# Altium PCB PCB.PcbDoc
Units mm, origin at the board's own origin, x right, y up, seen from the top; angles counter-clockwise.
Board outline 41 x 25.36 mm, 2 copper layers (TOP, BOTTOM), stack 1.586 mm thick; 64 components, 42 nets, 181 pads, 89 vias.
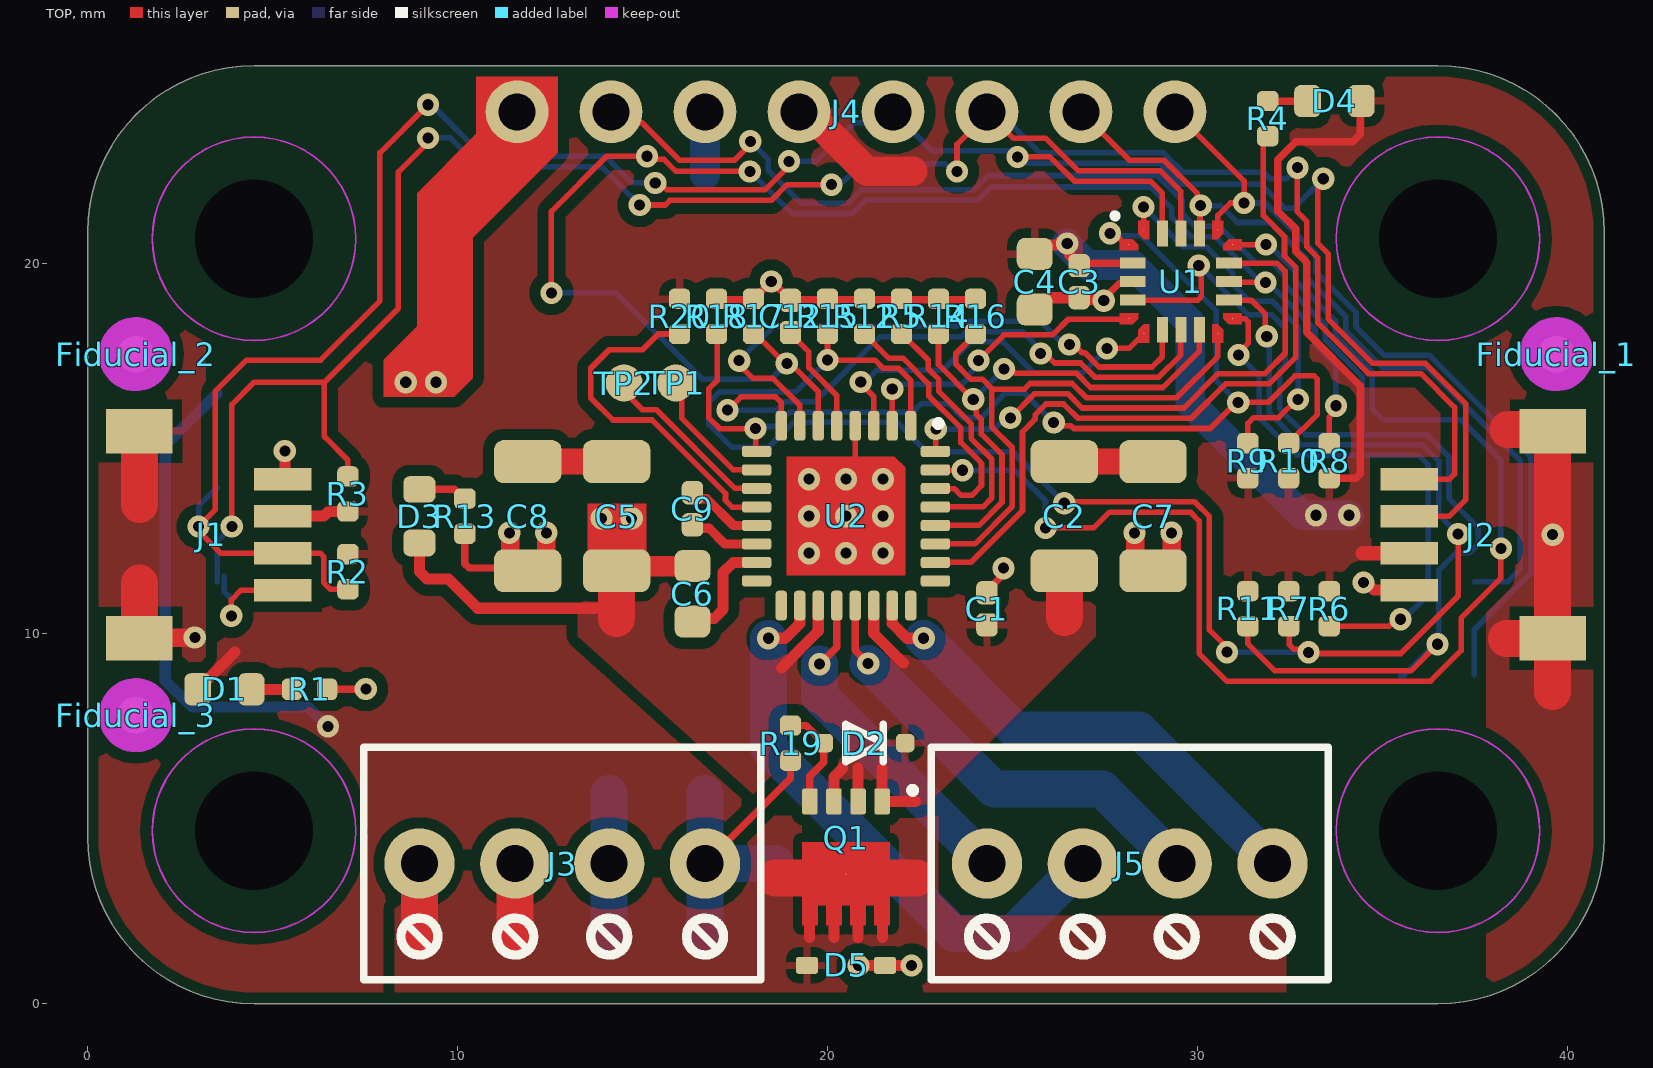
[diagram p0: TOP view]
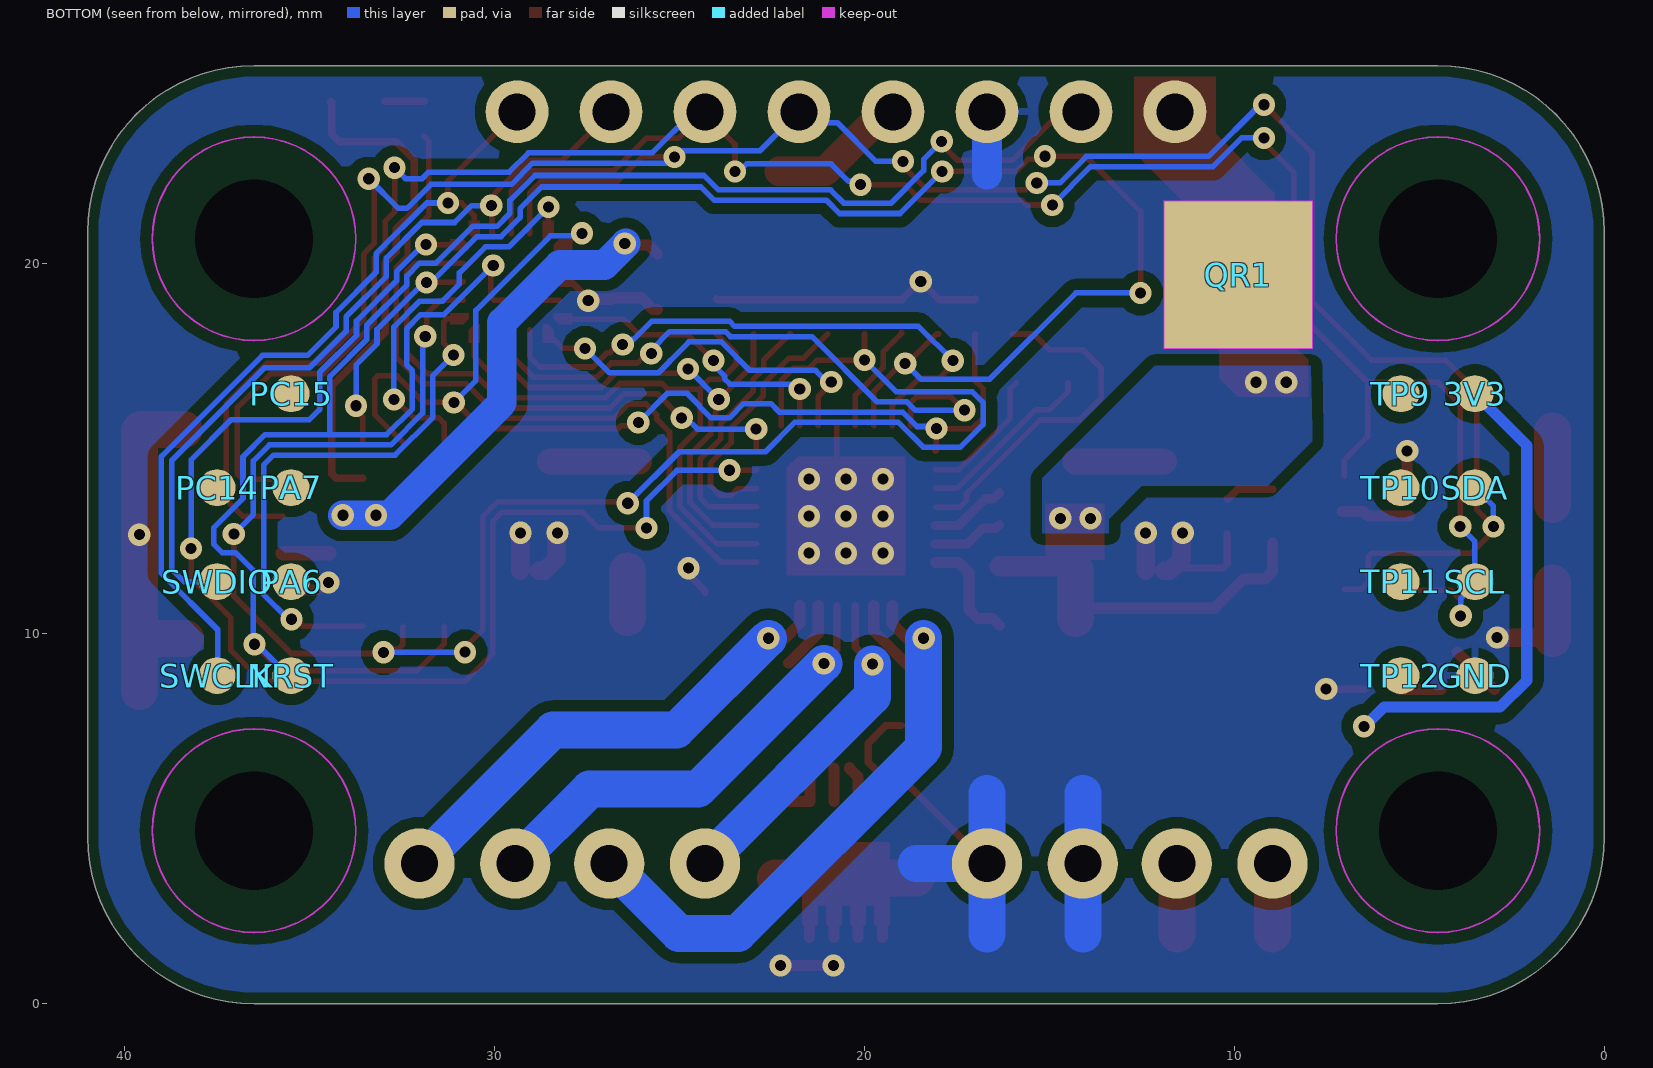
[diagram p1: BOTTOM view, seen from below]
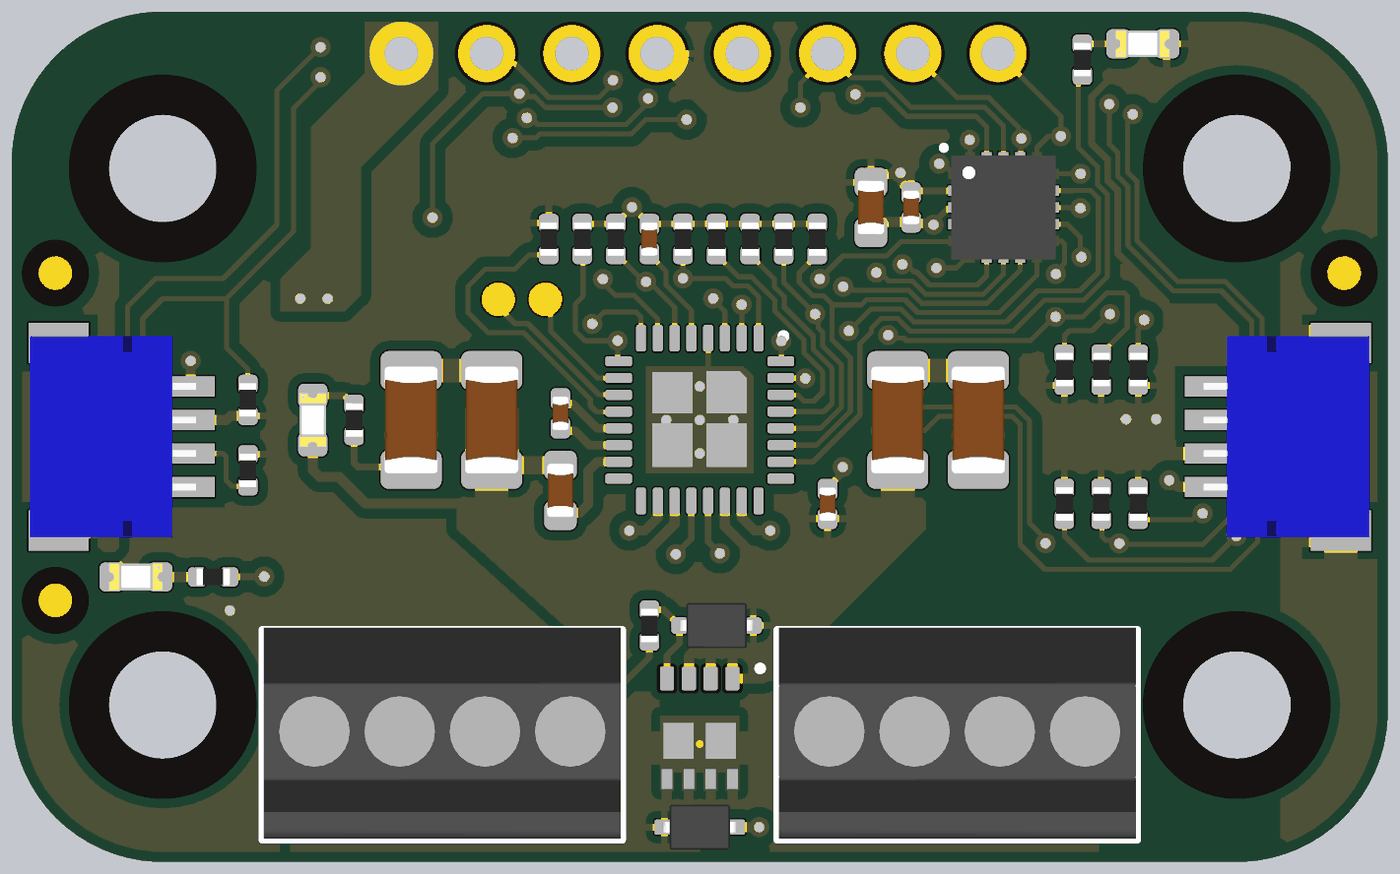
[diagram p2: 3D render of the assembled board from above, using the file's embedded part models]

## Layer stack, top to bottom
Top Solder: solder mask 0.01, Solder Resist, Dk 3.5
TOP: signal copper 0.018
Dielectric: core 1.55, FR-4, Dk 4.8
BOTTOM: signal copper 0.018
Bottom Solder: solder mask 0.01, Solder Resist, Dk 3.5

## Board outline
0,4.5 ccw(c4.5,4.5) 4.5,0 36.5,0 ccw(c36.5,4.5) 41,4.5 41,20.86 ccw(c36.5,20.86) 36.5,25.36 4.5,25.36 ccw(c4.5,20.86) 0,20.86

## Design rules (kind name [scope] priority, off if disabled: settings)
BoardOutlineClearance Mousebites [(ObjectKind = 'Pad') And (Name = 'Free-MOUSEBITE')] p1: gap=0 ignorepadtopadclearanceinfootprint=FALSE
BoardOutlineClearance Silks [(OnLayer('Top Overlay') OR OnLayer('Bottom Overlay'))] p2: gap=0 ignorepadtopadclearanceinfootprint=FALSE
BoardOutlineClearance [All] p3: gap=0.3 ignorepadtopadclearanceinfootprint=FALSE
Clearance VMOTOR_clearance [InNet('VMOTOR')] p1: gap=0.198 ignorepadtopadclearanceinfootprint=FALSE
Clearance COPPER_0.3mm [All] p2: gap=0.127 ignorepadtopadclearanceinfootprint=FALSE except(0.3: Arc-Fill Arc-Poly Arc-Region Track-Fill Track-Poly Track-Region SMDPad-Fill SMDPad-Poly SMDPad-Region THPad-Fill THPad-Poly THPad-Region Via-Fill Via-Poly Via-Region Fill-Fill Fill-Poly Fill-Region Poly-Poly Poly-Region Region-Region)
Clearance "Generic clearance 0.15mm" [All] p3: gap=0.127 ignorepadtopadclearanceinfootprint=FALSE
ComponentClearance [All] p1: gap=0.2 collisioncheckmode=3 verticalgap=0 showdistances=TRUE
DiffPairsRouting USB [InDifferentialPairClass('USB')] p1: maxlimit=0.15 minlimit=0.15 mostfreqgap=0.15 toplayer_minwidth=0.15 toplayer_maxwidth=0.21 toplayer_prefwidth=0.2 bottomlayer_minwidth=0.15 bottomlayer_maxwidth=0.21 bottomlayer_prefwidth=0.2 impedanceprofiledriven=TRUE impedanceprofileid={E6B00C31-4C8E-439C-824F-D2B2CDC26F9C} impedanceprofilevalue=90.000000 maxuncoupledlength=12.7
Height [All] p1: minheight=0 maxheight=30 prefheight=12.7
HoleSize [All] p1: absolutevalues=TRUE maxlimit=30 minlimit=0.3 maxpercent=80.000 minpercent=20.000
HoleToHoleClearance [All] p1: gap=0.25 allowstackedmicrovias=FALSE
MinimumAnnularRing [All] p1: minimumring=0.15
PlaneConnect [All] p1: pad.planeconnectstyle=Relief pad.reliefexpansion=0.508 pad.reliefentries=4 pad.reliefconductorwidth=0.254 pad.reliefairgap=0.254 via.planeconnectstyle=Direct via.reliefexpansion=0.508 via.reliefentries=4 via.reliefconductorwidth=0.254 via.reliefairgap=0.254
PolygonConnect QR_POLYGONCONNECT [(ObjectKind = 'Pad') And (Name = 'QR1-PAD')] p1: connectstyle=Direct reliefconductorwidth=0.254 reliefentries=4 polygonreliefangle="90 Angle" airgapwidth=0.254
PolygonConnect [All] p2: thpad.connectstyle=Relief thpad.reliefconductorwidth=0.2 thpad.reliefentries=4 thpad.polygonreliefangle="90 Angle" thpad.airgapwidth=0.254 smdpad.connectstyle=Relief smdpad.reliefconductorwidth=0.2 smdpad.reliefentries=4 smdpad.polygonreliefangle="90 Angle" smdpad.airgapwidth=0.254 via.connectstyle=Direct via.reliefconductorwidth=0.254 via.reliefentries=4 via.polygonreliefangle="90 Angle" via.airgapwidth=0.254
RoomDefinition U_MICROCONTROLLER [InComponentClass('U_MICROCONTROLLER')] p1: confinementstyle=ConfineIn formatcopy=TRUE lockcomponents=FALSE outline 45.91,3.64 52.06,3.64 52.06,20.72 45.91,20.72
RoomDefinition TOP [InComponentClass('TOP')] p2: confinementstyle=ConfineIn formatcopy=TRUE lockcomponents=FALSE outline 45.91,5.89 51.16,5.89 51.16,19.24 45.91,19.24
RoutingVias StandardVias [All] p1: holewidth=0.3 width=0.6 viastyle="Through Hole" minholewidth=0.3 minwidth=0.6 maxholewidth=0.3 maxwidth=0.6
SilkToSilkClearance [All] p1: silktosilkclearance=0.2
SilkToSolderMaskClearance [IsPad] p1: minsilkscreentomaskgap=0.15 clearancetoexposedcopper=TRUE
SolderMaskExpansion VIAtented [IsVia] p1: expansion=0.102 istentingtop=TRUE
SolderMaskExpansion [All] p2: expansion=0.05 istentingtop=FALSE
SupplyNets "Schematic Supply Nets_3" [InNet('VM')] p1: voltage=0.000
SupplyNets "Schematic Supply Nets_2" [InNet('GND')] p2: voltage=0.000
SupplyNets "Schematic Supply Nets" [InNet('+3V3')] p3: voltage=0.000
UnConnectedPin [All] p1:
UnRoutedNet [NOT WithinRoom('K36')] p1: checkbadconnections=TRUE
ViasUnderSMD [All] p1: allowed=FALSE
Width StandardTraces [All] p1: maxlimit=5 minlimit=0.15 preferedwidth=0.15 minimp=50.000000 maximp=50.000000 favimp=50.000000
21 further rules are at their usual default settings.

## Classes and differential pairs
component class U_MICROCONTROLLER: C3 C4 R2 R3 R6 R7 R8 R9 R10 R11 U1
component class U_MOTOR_CONTROLLER: C1 C2 C5 C6 C7 C8 C9 C12 R5 R12 U2
component class TOP: 3V3 D1 D2 D3 D4 D5 Fiducial_1 Fiducial_2 Fiducial_3 GND J1 J2 J3 J4 J5 NRST PA6 PA7 PC14 PC15 Q1 QR1 R1 R4 R13 R14 R15 R16 R17 R18 R19 R20 SCL SDA SWCLK SWDIO TP1 TP2 TP9 TP10 TP11 TP12

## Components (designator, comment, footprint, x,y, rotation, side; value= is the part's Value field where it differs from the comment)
3V3 "Test point 1.00mm" TP-1.00MM 3.5,16.49 r90 bottom
C1 "GRM155R61H104KE19D" CAP-0402 24.31,10.675 r270 top value=100nF
C2 "GRM31CR61A107MEA8L" CAP-1206 26.4,13.18 r90 top value=100µF
C3 "0402B104K160CT" CAP-0402 26.8,19.52 r270 top value=100nF
C4 "GRM188R61C475KAAJD" CAP-0603 25.6,19.52 r90 top value=4.7µF
C5 "GRM31CR61A107MEA8L" CAP-1206 14.3,13.18 r90 top value=100µF
C6 "GRM188R61E105KA12J" CAP-0603 16.35,11.08 r270 top value=1µF
C7 "GRM31CR61A107MEA8L" CAP-1206 28.8,13.18 r270 top value=100µF
C8 "GRM31CR61A107MEA8L" CAP-1206 11.9,13.18 r270 top value=100µF
C9 "CL05B223KB5VPNC" CAP-0402 16.35,13.38 r270 top value=22nF
C12 "CC0402MRX5R5BB225" CAP-0402 19,18.579 r270 top value=2.2µF
D1 "LTST-C190KGKT" LEDC1608X80N-AK 3.7,8.5 r180 top
D2 "MM3Z6V2T1G" SOD323#1 21,7.047 r0 top
D3 "KPT-1608SECK" LEDC1608X80N-AK 8.97,13.18 r270 top
D4 "XHY-STB0603SR" LEDC1608X80N-AK 33.7,24.4 r0 top
D5 "SD24C-7" SOD323#2 20.5,1.037 r180 top
Fiducial_1 "Fiducial mark 1mm" "Fiducial mark 1mm-Footprint-1" 39.7,17.56 r270 top
Fiducial_2 "Fiducial mark 1mm" "Fiducial mark 1mm-Footprint-1" 1.3,17.56 r270 top
Fiducial_3 "Fiducial mark 1mm" "Fiducial mark 1mm-Footprint-1" 1.3,7.8 r270 top
GND "Test point 1.00mm" TP-1.00MM 3.5,8.87 r90 bottom
J1 "SM04B-SRSS-TB(LF)(SN)" SM04B-SRSS-TB(LF)(SN)-Footprint-1 3.337,12.68 r90 top locked
J2 "SM04B-SRSS-TB(LF)(SN)" SM04B-SRSS-TB(LF)(SN)-Footprint-1 37.663,12.68 r270 top locked
J3 "DG308-2.54-04P-13-00Z(H)" DG308-2.54-04P 12.83,3.79 r180 top
J4 "HEADER TH 2.54mm VERT. 1x008POS" "PIN HEADER 2.54mm VERT. 1x8POS" 20.5,24.11 r0 top
J5 "DG308-2.54-04P-13-00Z(H)" DG308-2.54-04P 28.17,3.79 r180 top
NRST "Test point 1.00mm" TP-1.00MM 35.5,8.87 r180 bottom
PA6 "Test point 1.00mm" TP-1.00MM 35.5,11.41 r180 bottom
PA7 "Test point 1.00mm" TP-1.00MM 35.5,13.95 r180 bottom
PC14 "Test point 1.00mm" TP-1.00MM 37.5,13.95 r180 bottom
PC15 "Test point 1.00mm" TP-1.00MM 35.5,16.49 r180 bottom
Q1 "DMP4025SFG-13" DMP4025SFG-13 20.5,3.97 r180 top
QR1 "QR CODE 4x4mm" "QR CODE 4x4mm" 9.9,19.7 r180 bottom
R1 "CRCW04021K00FKEDC" RES-0402 6,8.5 r180 top value=1k
R2 "RC0402FR-074K7L" RES-0402 7.039,11.68 r90 top value=4.7k
R3 "RC0402FR-074K7L" RES-0402 7.039,13.78 r270 top value=4.7k
R4 "CRCW04021K00FKEDC" RES-0402 31.9,23.925 r90 top value=1k
R5 "CRCW040247K0FKED" RES-0402 22,18.579 r270 top value=47k
R6 "RC0402FR-074K7L" RES-0402 33.563,10.68 r270 top value=4.7k
R7 "RC0402FR-074K7L" RES-0402 32.463,10.68 r270 top value=4.7k
R8 "RC0402FR-074K7L" RES-0402 33.563,14.68 r90 top value=4.7k
R9 "RC0402FR-074K7L" RES-0402 31.363,14.68 r90 top value=4.7k
R10 "RC0402FR-074K7L" RES-0402 32.463,14.68 r90 top value=4.7k
R11 "RC0402FR-074K7L" RES-0402 31.363,10.68 r270 top value=4.7k
R12 "CRCW040247K0FKED" RES-0402 21,18.579 r270 top value=47k
R13 "RC0402FR-074K7L" RES-0402 10.2,13.18 r90 top value=4.7k
R14 "RC0402FR-074K7L" RES-0402 23,18.579 r270 top value=4.7k
R15 "CRCW040247K0FKED" RES-0402 20,18.579 r270 top value=47k
R16 "RC0402FR-074K7L" RES-0402 24,18.579 r270 top value=4.7k
R17 "CRCW040247K0FKED" RES-0402 18,18.579 r270 top value=47k
R18 "CRCW040247K0FKED" RES-0402 17,18.579 r270 top value=47k
R19 "RC0402FR-074K7L" RES-0402 19,7.047 r90 top value=4.7k
R20 "CRCW040247K0FKED" RES-0402 16,18.579 r90 top value=47k
SCL "Test point 1.00mm" TP-1.00MM 3.5,11.41 r90 bottom
SDA "Test point 1.00mm" TP-1.00MM 3.5,13.95 r90 bottom
SWCLK "Test point 1.00mm" TP-1.00MM 37.5,8.87 r180 bottom
SWDIO "Test point 1.00mm" TP-1.00MM 37.5,11.41 r180 bottom
TP1 "Test point 1.00mm" TP-1.00MM 15.9,16.779 r0 top
TP2 "Test point 1.00mm" TP-1.00MM 14.5,16.779 r0 top
TP9 "Test point 1.00mm" TP-1.00MM 5.5,16.49 r0 bottom
TP10 "Test point 1.00mm" TP-1.00MM 5.5,13.95 r0 bottom
TP11 "Test point 1.00mm" TP-1.00MM 5.5,11.41 r0 bottom
TP12 "Test point 1.00mm" TP-1.00MM 5.5,8.87 r0 bottom
U1 "STM32C011F6U6TR" UFQFPN20 29.55,19.52 r0 top
U2 "MAX22211ATJ+T" QFN127P600-8N 20.5,13.18 r180 top

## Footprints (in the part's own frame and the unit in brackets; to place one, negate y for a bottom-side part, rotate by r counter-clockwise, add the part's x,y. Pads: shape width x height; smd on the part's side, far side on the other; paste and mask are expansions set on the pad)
CAP-0402 [mm] "Chip Capacitor, 2-Leads, Body  0402 (in) 1005 (mm), IPC Medium Density"
  rrect52% 0.63x0.58 smd mask+0.05: 1(-0.435,0) 2(0.435,0)
  body extent -0.5,-0.25 0.5,0.25, height 0.5
CAP-0603 [mm] "Chip Capacitor, Body 0603 imperial,1.6x0.8mm, IPC High Density"
  rrect51% 0.87x0.97 smd mask+0.05: 1(-0.75,0) 2(0.75,0)
  body extent -0.8,-0.4 0.8,0.4, height 0.8
CAP-1206 [mm] "Chip Capacitor, 2-Leads, 1206 (in) 3216 (mm), IPC Medium Density"
  rrect43% 1.16x1.82 smd mask+0.05: 1(-1.475,0) 2(1.475,0)
  body extent -1.6,-0.8 1.6,0.8, height 1.6
DG308-2.54-04P [mm]
  round 1.9 hole 1 mask+0.05: 1(-3.86,0) 2(-1.27,0) 3(1.27,0) 4(3.86,0)
  silkscreen extent -5.37,-3.14 5.37,3.14, body extent -5.32,-3.2 5.32,3.1, height 8.63
DMP4025SFG-13 [mm]
  round 0.025 smd paste-5 mask+0.1: D(0,0.455)
  rrect25% 0.42x0.7 smd mask+0.1: G(0.975,-1.5) S(-0.975,-1.5) S(-0.325,-1.5) S(0.325,-1.5)
  TOP region: 0.765,1.85 0.765,1.31 0.535,1.31 0.535,1.85 0.115,1.85 0.115,1.31 -0.115,1.31 -0.115,1.85 -0.535,1.85 -0.535,1.31 -0.765,1.31 -0.765,1.85 -1.185,1.85 -1.185,1.31 -1.185,-0.4 1.185,-0.4 1.185,1.85
  silkscreen extent -1.85,-1.85 -1.75,-1.75, body extent -1.62,-1.68 1.68,1.68, height 0.82
"Fiducial mark 1mm-Footprint-1" [mm]
  round 1 smd paste-10 mask+0.5: 1(0,0)
  TOP keep-out circle w1: c0,0 r0.5
LEDC1608X80N-AK [mm]
  rrect50% 0.72x0.87 smd: A(0.725,0) C(-0.725,0)
  body extent -0.8,-0.4 0.8,0.4, height 0.79
"PIN HEADER 2.54mm VERT. 1x8POS" [mm]
  round 1.7 hole 1 mask+0.1: 1(-8.89,0) 2(-6.35,0) 3(-3.81,0) 4(-1.27,0) 5(1.27,0) 6(3.81,0) 7(6.35,0) 8(8.89,0)
QFN127P600-8N [mm]
  rrect50% 0.3x0.8 smd mask+0.05: 1(-1.75,-2.44) 2(-1.25,-2.44) 3(-0.75,-2.44) 4(-0.25,-2.44) 5(0.25,-2.44) 6(0.75,-2.44) 7(1.25,-2.44) 8(1.75,-2.44) 17(1.75,2.415) 18(1.25,2.415) 19(0.75,2.415) 20(0.25,2.415) 21(-0.25,2.415) 22(-0.75,2.415) 23(-1.25,2.415) 24(-1.75,2.415)
  rrect50% 0.8x0.3 smd mask+0.05: 9(2.415,-1.75) 10(2.415,-1.25) 11(2.415,-0.75) 12(2.415,-0.25) 13(2.415,0.25) 14(2.415,0.75) 15(2.415,1.25) 16(2.415,1.75) 25(-2.415,1.75) 26(-2.415,1.25) 27(-2.415,0.75) 28(-2.415,0.25) 29(-2.415,-0.25) 30(-2.415,-0.75) 31(-2.415,-1.25) 32(-2.415,-1.75)
  round 0.025 smd paste-10 mask+0.05: 33(0,0)
  TOP region: -1.3,-1.6 -1.6,-1.32 -1.6,1.6 1.6,1.6 1.6,-1.6
  silkscreen extent -2.55,-2.55 -2.45,-2.45, body extent -2.5,-2.49 2.5,2.49, height 0.81
"QR CODE 4x4mm" [mm]
  rect 4x4 smd paste-2539.97 mask+0.1: PAD(0,0)
  TOP keep-out region: -2,2 2,2 2,-2 -2,-2
RES-0402 [mm] "Chip Resistor, 2-Leads, Body  0402 (in) 1005 (mm), IPC Medium Density"
  rrect51% 0.55x0.58 smd mask+0.05: 1(-0.475,0) 2(0.475,0)
  body extent -0.5,-0.25 0.5,0.25, height 0.34
SM04B-SRSS-TB(LF)(SN)-Footprint-1 [mm]
  rect 0.6x1.55 smd mask+0.05: 1(1.5,-1.937) 2(0.5,-1.937) 3(-0.5,-1.937) 4(-1.5,-1.937)
  rect 1.2x1.8 smd mask+0.05: FIX(-2.8,1.938) FIX(2.8,1.938)
  body extent -3,-2.16 3,2.8, height 2.98
SOD323#1 [mm] "Molded Diode, 2-Leads, Body 1,70x1,25mm, IPC High Density"
  rrect50% 0.5x0.5 smd: A(-1.1,0) C(1.1,0)
  silkscreen extent -0.51,-0.51 0.51,0.51, body extent -1.12,-0.67 1.12,0.67, height 1.11
SOD323#2 [mm] "Molded Diode, 2-Leads, Body 1,70x1,25mm, IPC High Density"
  rrect25% 0.59x0.45 smd: 1(-1.055,0) 2(1.055,0)
  body extent -1.12,-0.67 1.12,0.67, height 1.1
TP-1.00MM [mm]
  rrect100% 1x1 smd paste-2.54: X(0,0)
UFQFPN20 [mm] "QFN, 20-Leads, Body 3.00x3.00mm, Pitch 0.50mm, IPC Medium Density"
  round 0.025 smd mask+0.05: 1(-1.4,1) 5(-1.4,-1) 6(-1,-1.4) 10(1,-1.4) 11(1.4,-1) 15(1.4,1) 16(1,1.4) 20(-1,1.4)
  rect 0.7x0.3 smd mask+0.05: 2(-1.3,0.5) 3(-1.3,0) 4(-1.3,-0.5) 12(1.3,-0.5) 13(1.3,0) 14(1.3,0.5)
  rect 0.3x0.7 smd mask+0.05: 7(-0.5,-1.3) 8(0,-1.3) 9(0.5,-1.3) 17(0.5,1.3) 18(0,1.3) 19(-0.5,1.3)
  TOP region: 1.65,-0.85 1.65,-1.15 1.3,-1.15 1.15,-1 1.15,-0.85
  TOP region: -1.15,1.3 -1,1.15 -0.85,1.15 -0.85,1.65 -1.15,1.65
  TOP region: -1.15,1 -1.15,0.85 -1.65,0.85 -1.65,1.15 -1.3,1.15
  TOP region: -1.3,-1.15 -1.15,-1 -1.15,-0.85 -1.65,-0.85 -1.65,-1.15
  TOP region: 1,1.15 0.85,1.15 0.85,1.65 1.15,1.65 1.15,1.3
  TOP region: 1.65,1.15 1.65,0.85 1.15,0.85 1.15,1 1.3,1.15
  TOP region: 1.15,-1.65 0.85,-1.65 0.85,-1.15 1,-1.15 1.15,-1.3
  TOP region: -0.85,-1.65 -1.15,-1.65 -1.15,-1.3 -1,-1.15 -0.85,-1.15
  silkscreen extent -1.8,1.75 -1.75,1.8, body extent -1.55,-1.55 1.55,1.55, height 0.6

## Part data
3V3 GND NRST PA6 PA7 PC14 PC15 SCL SDA SWCLK SWDIO TP1 TP2 TP9 TP10 TP11 TP12: library part UT0013-A.6, Manufacturer="This is not a component"
C1: library part C0015-A.14, "CAP CHIP 0402 100nF 10% 50V X5R", Case Code (Imperial)=0402, Dielectric=X5R, Manufacturer=Murata, Tolerance=10%, Voltage=50V
C2 C5 C7 C8: library part C0166-A.1, "CAP CHIP 1206 100uF 20% 10V X5R", Case Code (Imperial)=1206, Dielectric=X5R, Manufacturer=Murata, Tolerance=20%, Voltage=10V
C3: library part C0012-A.15, "CAP CHIP 0402 100nF 10% 16V X7R", Case Code (Imperial)=0402, Dielectric=X7R, Manufacturer=Walsin, Tolerance=10%, Voltage=16V
C4: library part C0054-A.16, "CAP CHIP 0603 4.7uF 10% 16V X5R", Case Code (Imperial)=0603, Dielectric=X5R, Manufacturer=Murata, Manufacturer 3="Samsung Electro-Mechanics", Part number 2=GRM188R61C475KE11D, Part number 3=CL10A475KO8NNNC, Tolerance=10%, Voltage=16V
C6: library part C0044-A.14, "CAP CHIP 0603 1uF 10% 25V X5R", Case Code (Imperial)=0603, Dielectric=X5R, Manufacturer=Murata, Manufacturer 2=Hottech, Manufacturer 3="Samsung Electro-Mechanics", Part number 2=C1608A105K250NT, Part number 3=CL10A105KA8NNNC, Tolerance=10%, Voltage=25V
C9: library part C0119-A.8, "CAP CHIP 0402 22nF 10% 50V X7R", Case Code (Imperial)=0402, Dielectric=X7R, Manufacturer="Samsung Electro-Mechanics", Tolerance=10%, Voltage=50V
C12: library part C0076-A.13, "CAP CHIP 0402 2.2uF 20% 6.3V", Case Code (Imperial)=0402, Dielectric=X5R, Manufacturer=Yageo, Tolerance=20%, Voltage=6.3V
D1: library part L0009-A.6, "LED SMD 0603 GREEN/568 15mcd 120^", Manufacturer=Liteon
D2: library part D0086-3, "DIODE ZENER SMD 6V2 0.2W SOD323", Manufacturer=OnSemi, Power max=200mW
D3: library part L0006-A.5, "LED SMD 0603 ORANGE601 250mcd 120^", Manufacturer=Kingbright
D4: library part L0024-A.4, "LED SMD 0603 RED 625nm, water clear, 42 to 88 mcd, 120 degrees, 1.6x0.8x0.6mm", Manufacturer="Shenzen Corehy Technology"
D5: library part D0085-A.1, "DIODE TVS BIDIRECTIONAL 24V 70V SOD323", Manufacturer="Diodes Incorporated"
Fiducial_1 Fiducial_2 Fiducial_3: library part UT0023-A.7, "Fiducial mark 1mm clearance 2mm"
J1 J2: library part J0005-A.3, "CONN JST SH 1mm 4POS HORIZONTAL TIN QWIIC", LCSC Part #=C160404, Manufacturer=JST
J3 J5: library part J0438-A.5, "CONN SCREW TERMINAL 4 POS pitch 2.54mm height 8.6mm BLACK", Manufacturer=Degson
J4: library part J0171-A.4
Q1: library part T0059-A.2, "MOSFET P-CH Vds -40V, Vgs +-20V, RdsON 45mR at Vgs -4.5V, 3.3x3.3x0.8mm DFN", Drain to Source Voltage (Vdss)=40V, Gate to Source Voltage (Vgs)=10V, Manufacturer="Diodes Incorporated", Max Operating Temperature=150°C, Min Operating Temperature=-55°C
QR1: library part QR-0001-A.5, "QR CODE 4x4mm on layer 34 (This is not a component)", Manufacturer="This is not a component"
R1 R4: library part R0007-A.24, "RES CHIP 0402 1k 1% 1/16W", Case Code (Imperial)=0402, Manufacturer=Vishay, Power=62.5mW, Temperature Coefficient=100ppm, Tolerance=1%
R2 R3 R6 R7 R8 R9 R10 R11 R13 R14 R16 R19: library part R0013-A.24, "RES CHIP 0402 4k7 1% 1/16W", Case Code (Imperial)=0402, Manufacturer=YAGEO, Power=62.5mW, Temperature Coefficient=200ppm, Tolerance=1%
R5 R12 R15 R17 R18 R20: library part R0051-A.24, "RES CHIP 0402 47k 1% 1/16W", Case Code (Imperial)=0402, Manufacturer=Vishay, Power=62.5mW, Temperature Coefficient=200ppm, Tolerance=1%
U1: library part U0390-A.1, "IC Cortex M0, 32b MCU, 32KB Flash, 6KB RAM, VDD 2-3.6V, -40°C to 85°C, QFN20 3x3mm", Manufacturer="ST Microelectronics"
U2: library part U0300-A.2, "36V, 3.8A Two H-Bridge for Dual Brushed or Single Stepper Motor Drive", Manufacturer="Analoge Device"

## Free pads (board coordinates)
  round 3 hole 3.2 unplated paste-2539.97 mask+1.3: MH(4.5,4.68) MH(4.5,20.68) MH(36.5,4.68) MH(36.5,20.68)

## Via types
v1: diameter 0.6, hole 0.3, TOP to BOTTOM, tented both sides, 89 vias

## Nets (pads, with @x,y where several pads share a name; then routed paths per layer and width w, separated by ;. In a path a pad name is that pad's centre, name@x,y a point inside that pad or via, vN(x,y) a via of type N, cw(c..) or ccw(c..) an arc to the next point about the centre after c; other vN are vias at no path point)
+3V3: 3V3.X C3.1 C4.2 D1.A D4.A J1.2 J2.2 J4.4 R2.2 R3.2 R6.1 R7.1 R8.1 R9.1 R10.1 R11.1 R20.2 U1.2 | length 50.4
  TOP w0.15: D4.A D4.A@34.45,24.375
  TOP w0.2: C3.1@26.861,20.016 U1.2@28.046,20.016 ; R8.1 34.283,14.205 34.4,14.322 34.4,16.7 32.952,18.148 32.952,20.037 32.883,20.106 32.654,20.335 32.654,20.694 32.654,20.946 32.173,21.427 32.173,22.646 32.173,22.818 32.655,23.3 34.2,23.3 34.4,23.5 34.4,24.375 D4.A
  TOP w0.3: D1.A 3.98,9.505 ; J1.2 6.389,13.18 6.514,13.305 R3.2 R3.2@7.089,13.305 ; C4.2 25.841,20.511 26.203,20.511 26.321,20.629 26.399,20.551 v1(26.48,20.551) ; v1@26.538,20.608 v1(26.48,20.551) ; C3.1@26.861,20.016 C3.1 26.8,19.98 26.538,20.243 26.538,20.493 v1(26.48,20.551)
  TOP w0.4: 34.47,12.18 J2.2
  TOP w0.8: J4.4 19.46,24.11 21.07,22.5 22.3,22.5
  BOTTOM w0.3: 3V3.X 2.1,15.09 2.1,8.74 2.82,8.02 5.959,8.02 6.479,7.5 v1(6.5,7.5)
  BOTTOM w0.8: v1@26.449,20.551 27.03,19.97 28.245,19.97 29.801,18.414 29.801,16.242 32.839,13.204 v1(34.1,13.204)
  other v1: 33.2,13.204
GND: C1.1 C3.2 C4.1 C7.2 C8.2 C12.1 D5.1 GND.X J1.1 J1.FIX J2.1 J2.FIX J3.1 J3.2 J4.3 QR1.PAD R1.1 R5.1 R12.1 R13.1 R14.1 R15.1 R16.1 R17.1 R18.1 R19.1 U1.3 U2.4 U2.33 | length 55.5
  TOP w0.15: C8.2@11.688,11.917 C8.2 ; v1(20.5,13.18) 20.75,13.43 U2.4
  TOP w0.2: R1.1 6.48,8.505 7.517,8.505 v1(7.521,8.509) ; R13.1 10.2,11.897 10.317,11.78 11.825,11.78 C8.2 ; J3.1 19,6.1 R19.1 ; R18.1 17.02,19.034 R17.1@18,19.034 ; R17.1 18.012,19.054 18.479,19.522 v1(18.479,19.525) 18.497,19.525 19,19.022 C12.1 ; C12.1@18.98,19.034 C12.1 ; R16.1 23.98,19.034 19.02,19.034 C12.1 ; C1.1 24.31,11.163 24.683,11.535 24.683,11.699 v1(24.76,11.775) ; v1(27.467,19.004) 27.467,19.058 27.879,19.47 28.2,19.47 U1.3
  TOP w0.3: J1.1 5.332,14.238 v1(5.332,14.942) ; v1(20.837,1.037) D5.1 v1(22.273,1.037) ; C4.1 25.716,18.77 26.031,19.085 C3.2 26.84,19.045 27.427,19.045 v1(27.467,19.004) ; v1(34.486,11.383) 34.568,11.383 34.771,11.18 J2.1
  TOP w0.5: J1.FIX@1.399,9.88 1.419,9.9 v1(2.9,9.9) ; v1(11.4,12.73) 11.419,12.711 11.419,12.035 11.749,11.705 C8.2 ; C8.2@12.4,11.705 v1(12.4,12.73) ; v1(28.3,12.73) 28.319,12.711 28.319,12.035 28.649,11.705 C7.2 ; C7.2@29.3,11.705 v1(29.3,12.73)
  TOP w1: J1.FIX@1.399,9.88 1.399,11.379 ; 1.399,13.499 J1.FIX@1.399,15.48 ; 38.353,9.88 J2.FIX@39.601,9.88 ; 38.394,15.521 39.56,15.521 39.601,15.48 v1(39.601,12.68) J2.FIX@39.601,9.88 ; 39.601,8.443 J2.FIX@39.601,9.88
  BOTTOM w0.8: 16.69,22.41 J4.3
  BOTTOM w1: 14.1,1.89 J3.2 14.1,5.69 ; 16.69,1.89 J3.1 ; 16.69,5.69 J3.1 ; 18.59,3.79 J3.1
  other v1: 19.5,12.18 20.5,12.18 21.5,12.18 19.5,13.18 21.5,13.18 19.5,14.18 20.5,14.18 21.5,14.18
NetC2_2: C2.2 C7.1 | length 2.4
  TOP w0.7: C2.2@26.1,14.655 C7.1@28.5,14.655
NetC5_2: C5.2 C8.1 | length 2.4
  TOP w0.7: C8.1 C5.2
NetC6_2: C6.2 U2.15 | length 3
  TOP w0.288: C6.2@16.35,10.23 16.535,10.415 16.935,10.415 17.177,10.657 17.177,11.657 17.45,11.93 U2.15
NetC9_1: C9.1 U2.13 | length 2.1
  TOP w0.25: C9.1 16.513,13.652 16.734,13.652 17.457,12.93 U2.13
NetC9_2: C9.2 U2.14 | length 1.9
  TOP w0.25: C9.2 16.444,12.851 16.803,12.851 17.224,12.43 U2.14
NetC12_2: C12.2 U2.5 | length 3
  TOP w0.15: C12.2 19,18.119 19.498,17.621 19.498,17.196 20.25,16.444 U2.5
NetD1_C: D1.C R1.2 | length 1.1
  TOP w0.3: D1.C R1.2
NetD2_A: D2.A Q1.G R19.2 | length 2.8
  TOP w0.2: R19.2 19.425,7.522 D2.A ; Q1.G 19.525,6.155 19.9,6.53 D2.A@19.9,7.034
NetD3_C: D3.C R13.2 | length 1.3
  TOP w0.2: D3.C 9.913,13.905 10.163,13.655 R13.2
NetD4_C: D4.C R4.2 | length 1.1
  TOP w0.2: R4.2 D4.C
NetD5_2: D5.2 J3.3 J3.4 Q1.D | length 14.5
  TOP w0.3: 19.518,1.8 19.518,3.515 ; 20.173,1.8 20.173,3.515 ; 20.827,1.8 20.827,3.515 ; 21.482,1.8 21.482,3.515
  TOP w1: 8.97,1.89 J3.4 ; 11.56,1.89 J3.3 ; 18.6,3.395 20.5,3.395 22.4,3.395
NetR4_1: R4.1 U2.26 | length 20.1
  TOP w0.15: U2.26 23.873,11.93 25.27,13.327 25.27,15.458 25.611,15.799 25.611,15.918 25.905,16.212 26.384,16.212 26.77,15.827 29.831,15.827 30.76,16.756 31.937,16.756 32.65,17.47 32.65,19.912 32.352,20.21 32.352,20.732 31.782,21.302 31.782,22.682 31.782,23.332 R4.1
NetR5_2: R5.2 U2.29 | length 7.1
  TOP w0.15: R5.2 22.015,18.104 22.723,17.396 22.723,17.16 23.012,16.87 23.012,16.552 23.883,15.681 23.883,15.285 24.425,14.743 24.425,14.728 24.439,14.714 24.439,13.671 24.197,13.43 U2.29
NetR12_2: R12.2 U2.30 | length 7.1
  TOP w0.15: R12.2 21.654,17.45 22.04,17.45 22.735,16.756 22.735,16.436 23.606,15.565 23.606,15.17 24.148,14.628 24.148,14.613 24.162,14.599 24.162,14.006 23.9,13.744 23.608,13.744 23.431,13.922 22.923,13.922 U2.30
NetR20_1: R20.1 U2.12 | length 9.4
  TOP w0.15: R20.1 15.425,18.104 15,17.679 14.1,17.679 13.6,17.179 13.6,16.379 14.2,15.779 15.262,15.779 17.243,13.798 17.243,13.607 17.429,13.42 U2.12@18.075,13.42
NetTP1_X: TP1.X U2.10 | length 3.6
  TOP w0.15: TP1.X 16.063,16.616 16.063,15.823 17.455,14.43 U2.10
NetTP2_X: TP2.X U2.11 | length 4.9
  TOP w0.15: TP2.X 14.5,16.554 14.998,16.056 15.377,16.056 17.503,13.93 U2.11
OUT1A_1: J5.1 U2.23 | length 13.5
  TOP w0.3: U2.23 21.75,10.276 22.146,9.88 v1(22.6,9.88)
  BOTTOM w1: v1(22.6,9.88) 25.08,7.4 28.42,7.4 J5.1
OUT1B_1: J5.3 U2.18 | length 15.8
  TOP w0.3: v1(18.4,9.88) 18.854,9.88 19.25,10.276 U2.18
  BOTTOM w1: v1(18.4,9.88) 18.4,6.924 23.424,1.9 25.01,1.9 J5.3
OUT2A_1: J5.2 U2.21 | length 12.3
  TOP w0.2: U2.21 20.75,9.55 v1(21.1,9.2)
  BOTTOM w1: v1(21.1,9.2) 24.5,5.8 27.43,5.8 J5.2
OUT2B_1: J5.4 U2.20 | length 9
  TOP w0.2: v1(19.787,9.18) 20.25,9.642 U2.20
  BOTTOM w1: v1(19.787,9.18) 19.787,8.313 J5.4
PA0_TIM1_CH1_1: U1.5 U2.2 | length 8.3
  TOP w0.15: U2.2 v1(21.75,16.62) ; v1(24.077,17.388) 24.768,18.078 26.082,18.078 26.506,18.502 28.132,18.502 U1.5
  BOTTOM w0.15: v1(21.75,16.62) 21.872,16.62 22.002,16.75 23.639,16.75 23.779,16.89 23.779,16.968 24.077,17.266 v1(24.077,17.388)
PA1_TIM1_CH2_1: U1.6 U2.3 | length 10.2
  TOP w0.15: v1(20.9,16.804) 20.9,16.762 21.25,16.412 U2.3 ; v1(27.551,17.714) 28.144,17.714 U1.6
  BOTTOM w0.15: v1(20.9,16.804) 21.007,16.804 21.325,17.122 23.102,17.122 23.869,17.89 24.748,17.89 25.26,17.378 25.26,17.368 25.575,17.053 26.891,17.053 v1(27.551,17.714)
PA2_TIM1_CH3_1: U1.7 U2.7 | length 16
  TOP w0.15: v1(17.613,17.383) 17.613,17.274 17.983,16.904 18.526,16.904 19.25,16.18 U2.7 ; v1(26.537,17.823) 26.658,17.823 26.884,17.597 26.958,17.597 27.343,17.212 28.772,17.212 29.05,17.489 U1.7
  BOTTOM w0.15: v1(17.613,17.383) 18.542,18.312 23.508,18.312 23.64,18.444 25.756,18.444 26.236,17.964 26.273,17.964 26.415,17.823 v1(26.537,17.823)
PA3_TIM1_CH4_1: U1.8 U2.8 | length 16.9
  TOP w0.15: v1(17.297,16.045) 17.656,16.404 18.6,16.404 18.75,16.254 U2.8 ; v1(25.762,17.576) 25.883,17.576 26.139,17.32 26.843,17.32 27.229,16.935 28.952,16.935 29.55,17.533 U1.8
  BOTTOM w0.15: v1(17.297,16.045) 17.301,16.048 18.632,16.048 18.854,16.27 19.656,16.27 21.421,18.035 23.623,18.035 23.755,18.167 25.267,18.167 25.762,17.672 v1(25.762,17.576)
PA4_ADC1_IN4_1: R14.2 U1.9 U2.28 | length 15
  TOP w0.15: U2.28 24.089,12.93 24.716,13.557 24.716,14.844 24.16,15.4 24.16,15.796 24.024,15.932 24.024,16.253 v1(23.938,16.339) 23.935,16.339 23,17.274 R14.2 ; v1(24.772,17.156) 24.858,17.07 25.057,17.07 25.085,17.043 26.729,17.043 27.114,16.658 29.067,16.658 30.05,17.641 U1.9
  BOTTOM w0.15: v1(23.938,16.339) 23.946,16.339 24.764,17.156 v1(24.772,17.156)
PA5_ADC1_IN5_1: R16.2 U1.10 U2.27 | length 15.6
  TOP w0.15: U2.27 23.981,12.43 24.993,13.442 24.993,15.036 24.437,15.592 24.437,16.128 24.44,16.131 24.44,16.547 24.437,16.55 24.437,16.634 24.186,16.886 23.869,16.886 23.466,17.289 23.466,17.57 R16.2 ; 24.437,16.615 24.793,16.615 25.325,16.615 25.477,16.766 26.614,16.766 26.999,16.381 29.433,16.381 30.55,17.498 U1.10
PA6_2: R6.2 U1.11 | length 15
  TOP w0.15: U1.11 31.281,18.52 31.369,18.432 31.369,17.848 31.111,17.59 v1(31.111,17.535) ; R6.2 35.175,10.205 35.364,10.394 v1(35.486,10.394)
  BOTTOM w0.15: v1(31.111,17.535) 31.664,16.982 31.664,15.852 32.686,14.831 35.971,14.831 36.24,14.561 36.24,11.065 35.57,10.394 v1(35.486,10.394)
PA7: R7.2 R15.2 U1.12 U2.1 | length 48.6
  TOP w0.15: R15.2 v1(20,17.404) 20.004,17.4 21.28,17.4 21.507,17.173 21.926,17.173 22.25,16.849 22.25,16.83 22.252,16.828 22.252,16.412 22.25,16.41 U2.1 ; v1(26.4,13.53) 26.439,13.569 27.325,13.569 29.92,13.569 30.323,13.166 30.323,10.103 30.8,9.626 v1(30.8,9.504) ; U1.12 31.454,19.02 31.833,18.641 31.833,18.079 v1(31.871,18.041) ; R7.2 32.482,10.187 32.482,9.705 32.6,9.586 32.914,9.586 33.031,9.469 35.494,9.469 37.054,11.029 37.054,12.689 v1(37.046,12.697)
  BOTTOM w0.15: v1(20,17.404) 19.143,16.547 17.089,16.547 16.795,16.253 16.795,15.658 17.409,15.044 18.412,15.044 19.084,15.716 21.887,15.716 22.681,14.922 25.008,14.922 v1(26.4,13.53) ; v1(30.8,9.504) 30.802,9.502 32.998,9.502 v1(33,9.5) ; v1(31.871,18.041) 31.941,17.971 31.941,15.967 32.8,15.108 36.085,15.108 36.517,14.676 36.517,13.226 v1(37.046,12.697)
PA8: R8.2 R17.2 U1.13 U2.6 | length 41.3
  TOP w0.15: v1(12.538,19.215) 12.538,21.415 14.033,22.91 v1(15.123,22.91) 15.209,22.824 15.585,22.824 15.908,22.5 v1(17.9,22.5) ; R17.2 18.05,18.104 18.85,17.304 v1(18.9,17.304) 18.998,17.304 19.75,16.552 U2.6 ; U1.13 30.862,19.508 31.829,19.508 v1(31.841,19.496) ; R8.2 33.563,15.863 33.742,16.042 v1(33.742,16.164)
  BOTTOM w0.15: v1(12.538,19.215) 14.285,19.215 16.619,16.881 18.477,16.881 v1(18.9,17.304) ; v1(17.9,22.5) 19.038,21.362 20.674,21.362 21.033,21.721 24.066,21.721 24.422,22.077 28.726,22.077 29.307,21.496 29.307,21.253 29.823,20.737 30.478,20.737 31.719,19.496 31.91,19.496 33.177,18.229 33.177,17.837 33.742,17.272 v1(33.742,16.164)
PA11_1: U1.14 U2.32 | length 15.1
  TOP w0.15: U2.32 22.928,14.943 v1(22.928,15.533) ; v1(24.941,15.839) 25.591,16.489 26.499,16.489 26.885,16.104 29.631,16.104 30.56,17.033 31.822,17.033 32.373,17.584 32.373,19.797 32.148,20.022 31.642,20.022 31.64,20.02 U1.14
  BOTTOM w0.15: v1(22.928,15.533) 24.514,15.533 24.819,15.839 v1(24.941,15.839)
PA12_1: U1.15 U2.31 | length 36
  TOP w0.15: U2.31@22.917,14.432 U2.31 22.92,14.425 23.641,14.425 v1(23.646,14.42) ; v1(25.893,12.862) 27.192,12.862 27.622,13.292 29.805,13.292 30.046,13.052 30.046,9.463 30.788,8.721 36.298,8.721 37.124,9.547 37.124,10.428 38.2,11.504 v1(38.2,12.304) ; U1.15 31.846,20.52 v1(31.85,20.524)
  BOTTOM w0.15: v1(23.646,14.42) 25.069,14.42 25.893,13.597 v1(25.893,12.862) ; v1(31.85,20.524) 31.914,20.524 32.646,19.792 32.646,19.543 33.731,18.458 33.731,18.066 34.728,17.069 34.728,16.063 35.003,15.788 37.116,15.788 38.202,14.702 38.202,12.306 v1(38.2,12.304)
PA13_SWDIO_1: J4.8 SWCLK.X U1.16 | length 22.1
  TOP w0.15: J4.8 31.259,22.241 v1(31.259,21.645) 30.887,21.645 30.55,21.307 U1.16
  BOTTOM w0.15: v1(31.259,21.645) 31.831,21.645 33.2,20.276 33.2,19.773 34.285,18.688 34.285,18.296 35.057,17.524 36.272,17.524 39.003,14.793 39.003,11.633 37.48,10.11 SWCLK.X@37.48,8.899
PA14_SWCLK_BOOT0_1: J4.7 SWDIO.X U1.17 | length 21.5
  TOP w0.15: J4.7 28.16,22.8 29.1,22.8 30,21.9 30,21.661 v1(30.086,21.575) 30.068,21.557 30.068,20.838 U1.17
  BOTTOM w0.15: v1(30.086,21.575) 30.618,21.575 31.076,21.117 31.966,21.117 32.923,20.161 32.923,19.658 34.008,18.573 34.008,18.181 34.997,17.192 36.212,17.192 38.726,14.678 38.726,11.748 38.388,11.41 SWDIO.X
PC14_2: R9.2 U1.20 | length 10.4
  TOP w0.15: v1(28.542,21.534) 28.55,21.526 U1.20 ; R9.2 31.363,15.69 31.516,15.843 32.191,15.843 32.685,16.338 v1(32.72,16.338)
  BOTTOM w0.15: v1(28.542,21.534) 29.616,20.46 30.243,20.46 30.949,19.754 30.949,19.451 31.406,18.994 32.02,18.994 32.72,18.294 v1(32.72,16.338)
PC15: R10.2 R18.2 U1.1 U2.9 | length 30.5
  TOP w0.15: R18.2 17.02,18.084 17.02,16.851 16.795,16.626 16.795,15.837 17.089,15.543 18.052,15.543 v1(18.055,15.546) 18.055,14.96 U2.9 ; v1(26.113,15.71) 26.199,15.624 26.581,15.624 26.655,15.55 30.346,15.55 v1@31.075,16.279 ; v1(27.632,20.825) 27.754,20.825 28.059,20.52 U1.1 ; v1(31.1,16.254) 31.914,16.254 32.633,16.974 33.152,16.974 33.24,16.886 33.24,15.932 R10.2
  BOTTOM w0.15: v1(18.055,15.546) 18.114,15.604 18.58,15.604 18.969,15.993 22.305,15.993 22.532,16.22 23.272,16.22 23.655,15.837 24.146,15.837 24.469,16.16 24.469,16.179 24.792,16.502 25.321,16.502 v1(26.113,15.71) ; v1(27.632,20.825) 27.703,20.755 28.492,20.755 30.503,18.744 30.503,16.851 v1(31.1,16.254)
PF2_N\R\S\T\_1: J4.2 NRST.X R11.2 U1.4 | length 53.4
  TOP w0.15: J4.2 14.447,23.813 14.987,23.813 16,22.8 17.49,22.8 17.915,23.225 v1(17.915,23.311) ; U1.4 30.012,19.02 30.1,19.108 30.1,19.893 v1(30.036,19.958) ; R11.2 31.363,9.729 32.094,8.998 35.77,8.998 v1(36.49,9.718)
  BOTTOM w0.15: v1(17.915,23.311) 18.402,22.824 18.402,22.52 19.283,21.639 20.559,21.639 20.919,21.998 23.951,21.998 24.342,22.389 28.911,22.389 29.584,21.716 29.584,21.367 29.938,21.014 30.593,21.014 31.585,20.022 32.025,20.022 32.369,19.678 32.369,19.428 33.454,18.343 33.454,17.952 34.451,16.955 34.451,15.385 ; v1(30.036,19.958) 31.367,18.626 31.996,18.626 32.373,18.249 32.373,17.267 32.218,17.112 32.218,16.082 32.915,15.385 34.451,15.385 ; NRST.X 35.571,8.87 36.419,9.718 v1(36.49,9.718) 36.517,9.746 36.517,11.71 37.002,12.195 37.364,12.195 37.586,12.417 37.586,12.871 36.798,13.659 36.798,14.787 36.2,15.385 34.451,15.385
SCL_1: J1.4 J2.4 J4.6 R3.1 SCL.X U1.18 | length 67.6
  TOP w0.15: v1(3.886,10.486) 3.886,10.916 4.15,11.18 J1.4 ; v1(3.9,12.9) 3.9,16.2 4.5,16.8 6.4,16.8 ; R3.1 7.039,14.691 6.4,15.33 6.4,16.8 ; v1(9.2,23.404) 9.2,23.282 8.4,22.482 8.4,18.8 6.4,16.8 ; v1(14.923,21.591) 15.614,21.591 15.739,21.716 18.48,21.716 18.904,22.141 v1(20.111,22.141) ; v1(23.5,22.5) 23.5,23.228 24.31,24.038 J4.6 25.028,23.393 25.902,23.393 26.784,22.511 28.997,22.511 29.55,21.958 U1.18 ; v1(32.7,22.6) 32.7,21.406 32.956,21.15 32.956,20.46 33.185,20.231 33.254,20.162 33.254,18.4 34.62,17.034 35.545,17.034 36.036,17.034 36.95,16.12 36.95,14.32 36.81,14.18 J2.4
  BOTTOM w0.15: SCL.X 3.5,12.5 v1(3.9,12.9) ; SCL.X@3.694,11.557 3.694,11.14 3.886,10.948 v1(3.886,10.486) ; v1(9.2,23.404) 9.271,23.333 9.342,23.404 9.808,23.404 10.585,22.627 13.887,22.627 v1(14.923,21.591) ; v1(20.111,22.141) 20.197,22.227 20.427,22.227 20.9,22.7 23.187,22.7 23.387,22.5 v1(23.5,22.5) ; J4.6 24.628,24.11 25.738,23 29.083,23 29.606,22.477 31.782,22.477 31.953,22.306 32.406,22.306 v1(32.7,22.6)
SDA_1: J1.3 J2.3 J4.5 R2.1 SDA.X U1.19 | length 67.5
  TOP w0.15: R2.1 6.564,11.205 6.49,11.28 6.389,11.38 6.389,12.08 6.289,12.18 J1.3 3.598,12.18 3.186,12.592 3,12.778 v1(3,12.9) 3.448,13.348 3.448,16.548 4.3,17.4 6.3,17.4 7.9,19 7.9,23 v1(9.2,24.3) ; v1(15.346,22.189) 15.467,22.189 15.658,21.998 18.309,21.998 18.96,22.65 v1(18.96,22.772) ; v1(25.138,22.891) 26.012,22.891 26.669,22.234 28.726,22.234 29.05,21.91 U1.19 ; v1(33.4,22.3) 33.4,22.178 33.247,22.026 33.247,20.56 33.531,20.277 33.531,18.515 34.735,17.311 36.159,17.311 37.25,16.22 37.25,13.62 36.81,13.18 J2.3
  BOTTOM w0.15: v1(3,12.9) 3,13.45 SDA.X ; v1(9.2,24.3) 9.304,24.3 10.7,22.904 14.002,22.904 14.717,22.189 v1(15.346,22.189) ; v1(18.96,22.772) 19.692,22.772 20.734,23.813 21.473,23.813 J4.5 22.822,23.058 24.97,23.058 v1(25.138,22.891) 25.305,22.723 28.969,22.723 29.545,22.147 31.721,22.147 32.367,21.501 32.601,21.501 v1(33.4,22.3)
VM: C1.2 C2.1 C5.1 C6.1 D2.C D3.A J4.1 Q1.S U2.19 U2.22 | length 21.6
  TOP w0.2: 14.182,10.29 14.3,10.408
  TOP w0.3: D3.A 8.97,11.687 9.176,11.481 9.755,11.481 10.543,10.693 14.3,10.693 ; 18.756,9.081 19.75,10.075 U2.19 ; Q1.S@20.175,5.47 20.177,5.472 20.177,6.135 20.408,6.366 20.408,6.38 ; Q1.S@20.825,5.47 20.825,6.375 ; U2.22 21.25,10.009 22.047,9.212 ; 21.475,6.375 21.475,5.47 22.38,5.47
  TOP w0.55: v1(13.892,13.122) 14.304,12.711 C5.1@14.304,11.709 ; 14.304,12.718 C5.1@14.304,11.709 ; C6.1 14.425,11.83 C5.1 C5.1@14.304,11.709
  TOP w1: 14.3,10.408 C5.1 ; 26.4,10.448 C2.1
  other v1: 14.708,13.122 8.6,16.8 9.415,16.8
pads on no net: Fiducial_1.1 Fiducial_2.1 Fiducial_3.1 PA6.X PA7.X PC14.X PC15.X TP9.X TP10.X TP11.X TP12.X U2.16 U2.17 U2.24 U2.25

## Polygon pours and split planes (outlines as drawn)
+3V3 on TOP "NONET_L04_P-001" (solid, remove dead copper, pour order 6): 0,4.5 ccw(c4.5,4.5) 4.5,0 36.5,0 ccw(c36.5,4.5) 41,4.5 41,20.86 ccw(c36.5,20.86) 36.5,25.36 4.5,25.36 ccw(c4.5,20.86) 0,20.86
VM on TOP "NONET_L04_P-001" (solid, remove dead copper, pour order 2): 27.25,12.43 27.25,9.93 22.647,5.327 18.365,5.327 13.25,9.93 13.25,12.43
NetD5_2 on TOP "NONET_L-01_P-001" (solid, remove dead copper, pour order 1): 17.8,3.7 17.8,5.085 22.99,5.085 22.99,2.984 23.6,2.374 32.4,2.374 32.4,0 8.3,0 8.3,3.7
GND on TOP "NONET_L04_P-001" (solid, remove dead copper, pour order 5): 41,25.36 41,0 37.8,0 37.8,25.36
GND on TOP "NONET_L04_P-001" (solid, remove dead copper, pour order 4): 0,25.36 0,0 3.2,0 3.2,25.36
GND on BOTTOM "NONET_L04_P-001" (solid, remove dead copper, pour order 7): 0,4.5 ccw(c4.5,4.5) 4.5,0 36.5,0 ccw(c36.5,4.5) 41,4.5 41,20.86 ccw(c36.5,20.86) 36.5,25.36 4.5,25.36 ccw(c4.5,20.86) 0,20.86
VM on BOTTOM "VM_L02_P003" (solid, remove dead copper, pour order 3): 7.934,17.246 12.154,17.246 15.2,14.2 15.2,12.713 13.4,12.713 13.4,13.1 12.5,14 9.1,14 7.9,15.2 7.9,15.5

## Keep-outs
Keep-Out Layer:
  circle w0.05: c36.5,4.68 r2.75
  circle w0.05: c36.5,20.68 r2.75
  circle w0.05: c4.5,4.68 r2.75
  circle w0.05: c4.5,20.68 r2.75

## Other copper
TOP:
  rectangle net VM: 13.508,12 15.108,13.525
  region net VM: 12.71,25.054 12.71,23.01 10.41,20.71 10.41,16.906 9.91,16.413 8.008,16.413 8.008,17.413 8.908,18.313 8.908,21.913 10.51,23.515 10.51,25.054
  pour cut-out: 19.3,2.1 19.3,4.9 21.7,4.9 21.7,2.1

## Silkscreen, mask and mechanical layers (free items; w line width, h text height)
Route Tool Path:
  lines w2: -1,8.498 -1,16.86 ; -1,20.86 cw(c4.5,20.86) 4.5,26.36 ; 42,4.5 cw(c36.5,4.5) 36.5,-1 ; 42,8.498 42,16.86 ; -1,4.498 ccw(c4.5,4.5) 4.498,-1 ; -1,4.498 cw(c4.5,4.5) -1,4.5 ccw(c0,4.5) -1,4.498 ; 4.498,-1 ccw(c4.5,4.5) 4.5,-1 ; 4.498,-1 ccw(c4.5,0) 4.5,-1 ; 4.5,-1 36.5,-1 ; 4.5,26.36 36.5,26.36 ; 4.5,26.36 4.5,26.36 ; 36.5,-1 36.5,-1 ; 36.5,26.36 cw(c36.5,20.86) 36.502,26.36 ; 36.5,26.36 cw(c36.5,25.36) 36.502,26.36 ; 36.502,26.36 cw(c36.5,20.86) 42,20.863 ; 42,20.863 cw(c41,20.86) 42,20.86 ccw(c36.5,20.86) 42,20.863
